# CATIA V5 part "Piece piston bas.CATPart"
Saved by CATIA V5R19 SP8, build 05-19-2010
Part number: Piece piston bas
Bounding box of the stored display mesh (mm): x -79.673 to -4.924, y -127.831 to 21.344, z -11.804 to 11.804
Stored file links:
  G:\EU_thinkMotion\CFAO_2010\MMS_groupe3\MMS_groupe3\A reprendre\lpastor\lpastor\Piece piston bas.CATPart
  C:\Users\Loïc\Documents\IFMA\Cours 2A\CFAO\Thinkmotion\Fourche avant.CATProduct
  G:\EU_thinkMotion\CFAO_2010\MMS_groupe3\MMS_groupe3\A reprendre\lpastor\lpastor\Piece piston haut.CATPart
  G:\EU_thinkMotion\CFAO_2010\MMS_groupe3\MMS_groupe3\A reprendre\lpastor\lpastor\Pieces.CATProduct
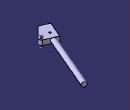
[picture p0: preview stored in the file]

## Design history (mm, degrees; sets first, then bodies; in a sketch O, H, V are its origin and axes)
External parameters (linked from other documents)
  External.Parametre_rayon_interieur_rotule_basse = 0.003
  External.Parametre_rayon_interieur_amortisseur_haut = 0.005
Set1
  Plane1: linked copy from another document
  DatumCurve1: linked copy from another document
  Plane2: linked copy from another document
  Line1 "Droite GH (piston bas)": linked copy from another document
  Plane3: linked copy from another document
  Line2 "Droite F (piston bas)": linked copy from another document
  Point1 "G": linked copy from another document
  Line3 "Droite G (piston bas)": linked copy from another document
  Plane4: linked copy from another document
Body1 (main body)
  Sketch1 on Plane2, origin (0, 0, 5), H (1, 0, 0), V (0, 1, 0)
    line L1 (-65.9752, -87.7955) -> (-41.0432, -98.3988)
    arc A1 centre (-43, -103) radius 5 from (-41.0432, -98.3988) to (-39.5064, -106.577) cw
    point P3 (-43, -103)
    line L2 (-61.2683, -127.8311) -> (-79.673, -120.0038)
    line L3 (-79.673, -120.0038) -> (-65.9752, -87.7955)
    reference projected line E1 (-62, -104) -> (12, 70) from Line1
    reference projected point E2 (-43, -103) from Line2
    reference projected point E3 (-43, -103) from Line2
    reference projected line E4 (-62, -104) -> (12, 70) from Line1
    line L4 (-61.2683, -127.8311) -> (-39.5064, -106.577)
    circle A2 centre (-62, -104) radius 2
    point P7 (-62, -104)
    reference projected point E5 (-62, -104) from Line3
    distance E3 L1 = 5
    distance E4 L3 = 10
    length L3 = 35
    length L2 = 20
    radius A2 = 2
    tangency: A1 L1, L4 A1
    parallelism: L2 L1
    perpendicularity: L3 L1, L1 E1
    coincidence: P3 E2, P7 E5
  Pad1: profile Sketch1, direction (0, 0, -1), up to Plane4
  Sketch2 on Plane3, origin (0, 0, 9), H (1, 0, 0), V (0, 1, 0)
    arc A1 centre (-43, -103) radius 3 from (-43, -106) to (-43, -100) ccw
    point P1 (-43, -103)
    line L1 (-43, -100) -> (-43, -106)
    reference projected point E1 (-43, -103) from Line2
    radius A1 = 3 {= External.Parametre_rayon_interieur_rotule_basse}
    vertical: L1 V
    coincidence: P1 E1
  Shaft1: profile Sketch2, axis Sketch2.L1, angle 360
  Sketch3 on Plane3, origin (0, 0, 9), H (1, 0, 0), V (0, 1, 0)
    circle A1 centre (-43, -103) radius 2
    point P1 (-43, -103)
    reference projected point E1 (-43, -103) from Line2
    radius A1 = 2
    coincidence: P1 E1
  Pad2: profile Sketch3, direction (0, 0, -1), up to start face of Pad1
  Mirror1: of Pad1, Shaft1, Pad2, about end face of Pad1
  Sketch4 on Plane1, origin (-23.8291, -56.0305, 0), H (-0.9202, 0.3914, 0), V (0, 0, 1)
    circle A1 centre (16.3527, 0) radius 5
    reference projected circle E1 centre (16.3527, 0) radius 5 from DatumCurve1
    radius A1 = 5 {= External.Parametre_rayon_interieur_amortisseur_haut}
    concentricity: A1 E1
  Pad3: profile Sketch4, direction (0.3914, 0.9202, 0), length 75, opposite side up to the existing solid (limit type 2)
